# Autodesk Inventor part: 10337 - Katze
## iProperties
Created: 2006-03
Part Number: 10337 - Katze
Document SubType Name: Modeling
Designer: Ebner
Manufacturer: Standard
Standards Organization: Custom
Masse: 0,000 kg
Flaeche: 000,0E+0mm^2
Volumen: 000,0E+0mm^3
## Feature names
1. Sweeping1
2. Sweeping2
3. Sweeping3
4. Erhebung1
5. Extrusion1
6. Extrusion2
7. Drehung1 [Revolution]
8. Drehung2 [Revolution]
